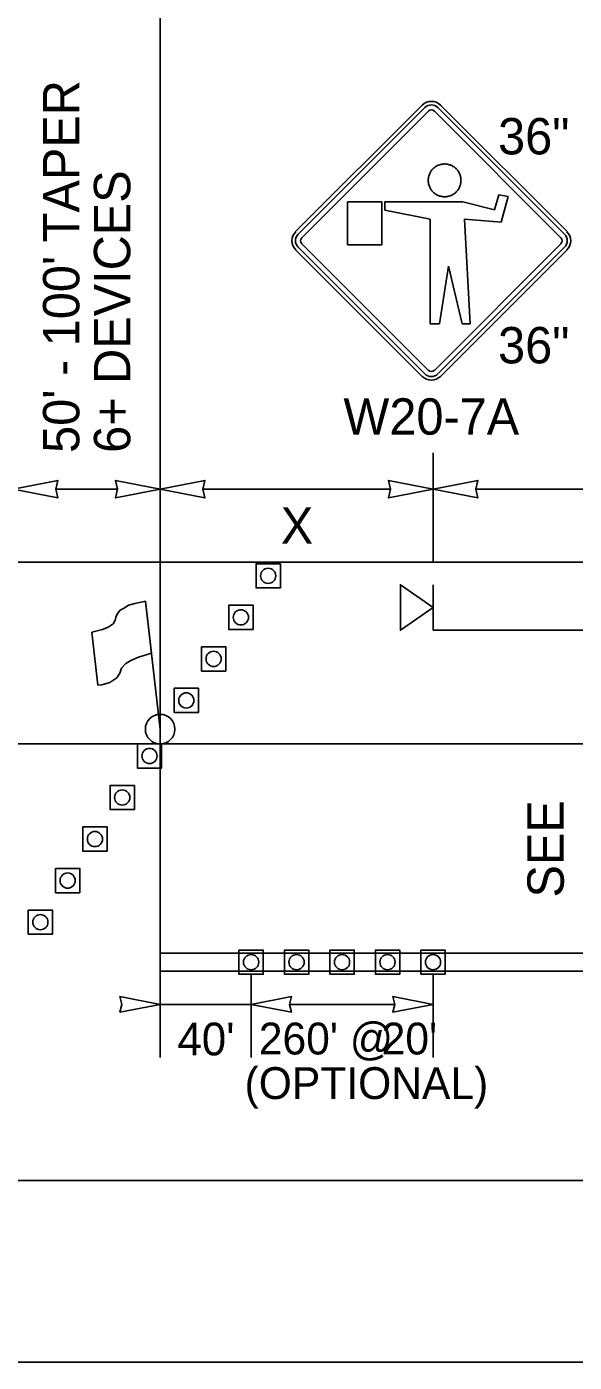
# Model space of a CAD drawing. Extents: x 99999.1 to 100095.7, y 99995 to 100010.7.
# Drawn here: x 100011.18 to 100012.384, y 100005.732 to 100008.67 of the extents above; entities that cross this region are included whole.
import ezdxf

# ---------------------------------------------------------------- set-up
doc = ezdxf.new("R2010")
doc.units = 0
for name, color, linetype in [('RD_ED_ShoulderPavedEdge', 7, 'Continuous'), ('RD_MK_LineDblYellowCenter', 7, 'Continuous'), ('RD_MK_LineEdgeWhite', 7, 'Continuous'), ('RD_MK_LineNoPass', 7, 'Continuous'), ('RD_MK_LineSkipCenter', 7, 'Continuous'), ('TR_SN_ConstructionSigns', 7, 'Continuous'), ('TR_WZ_FlaggingStation', 7, 'Continuous'), ('TR_WZ_PortableSignMountBlk-Org', 7, 'Continuous'), ('TR_WZ_TrafficCone', 7, 'Continuous'), ('TR_WZ_WorkZoneDetails', 7, 'Continuous'), ('TR_WZ_WorkZoneTextCurrent', 7, 'Continuous')]:
    doc.layers.add(name, color=color, linetype=linetype)

msp = doc.modelspace()

# ---------------------------------------------------------------- linework, layer by layer
at = {"layer": 'RD_ED_ShoulderPavedEdge'}
for p, q in [((100000.1076, 100007.4923), (100015.6424, 100007.4923)), ((100000.1076, 100005.7323), (100015.6424, 100005.7323))]:
    msp.add_line(p, q, dxfattribs=at)
at = {"layer": 'RD_MK_LineDblYellowCenter'}
for p, q in [((100012.2733, 100006.6323), (100015.6631, 100006.6323)), ((100012.2733, 100006.5923), (100015.6218, 100006.5923))]:
    msp.add_line(p, q, dxfattribs=at)
at = {"layer": 'RD_MK_LineEdgeWhite'}
for p, q in [((100000.1076, 100007.0923), (100015.6424, 100007.0923)), ((100000.1076, 100006.1323), (100015.6424, 100006.1323))]:
    msp.add_line(p, q, dxfattribs=at)
at = {"layer": 'RD_MK_LineNoPass'}
msp.add_line((100011.4733, 100006.5923), (100012.2733, 100006.5923), dxfattribs=at)
at = {"layer": 'RD_MK_LineSkipCenter'}
msp.add_lwpolyline([(100012.2733, 100006.6323), (100011.4733, 100006.6323)], dxfattribs=at)
at = {"layer": 'TR_SN_ConstructionSigns'}
for p, q in [((100012.0497, 100008.4972), (100011.7713, 100008.2188)), ((100012.0552, 100008.4917), (100011.7768, 100008.2132)), ((100011.7845, 100008.2055), (100012.063, 100008.4839)), ((100012.0762, 100008.4839), (100012.3546, 100008.2055)), ((100012.3624, 100008.2132), (100012.0839, 100008.4917)), ((100012.3679, 100008.2188), (100012.0895, 100008.4972)), ((100012.0797, 100008.3621), (100012.078, 100008.3611)), ((100012.0813, 100008.3631), (100012.0797, 100008.3621)), ((100012.083, 100008.364), (100012.0813, 100008.3631)), ((100012.0847, 100008.3648), (100012.083, 100008.364)), ((100012.0865, 100008.3655), (100012.0847, 100008.3648)), ((100012.0884, 100008.3661), (100012.0865, 100008.3655)), ((100012.0902, 100008.3666), (100012.0884, 100008.3661)), ((100012.0921, 100008.367), (100012.0902, 100008.3666)), ((100012.094, 100008.3673), (100012.0921, 100008.367)), ((100012.0959, 100008.3675), (100012.094, 100008.3673)), ((100012.0978, 100008.3676), (100012.0959, 100008.3675)), ((100012.0997, 100008.3676), (100012.0978, 100008.3676)), ((100012.1016, 100008.3675), (100012.0997, 100008.3676)), ((100012.1036, 100008.3673), (100012.1016, 100008.3675)), ((100012.1054, 100008.367), (100012.1036, 100008.3673)), ((100012.1073, 100008.3666), (100012.1054, 100008.367)), ((100012.1091, 100008.3661), (100012.1073, 100008.3666)), ((100012.111, 100008.3655), (100012.1091, 100008.3661)), ((100012.1128, 100008.3648), (100012.111, 100008.3655)), ((100012.1145, 100008.364), (100012.1128, 100008.3648)), ((100012.1162, 100008.3631), (100012.1145, 100008.364)), ((100012.1179, 100008.3621), (100012.1162, 100008.3631)), ((100012.1195, 100008.3611), (100012.1179, 100008.3621)), ((100012.063, 100008.3354), (100012.0628, 100008.3335)), ((100012.0628, 100008.3335), (100012.0628, 100008.3316)), ((100012.0632, 100008.3373), (100012.063, 100008.3354)), ((100012.0636, 100008.3392), (100012.0632, 100008.3373)), ((100012.064, 100008.3411), (100012.0636, 100008.3392)), ((100012.0646, 100008.3429), (100012.064, 100008.3411)), ((100012.0652, 100008.3447), (100012.0646, 100008.3429)), ((100012.066, 100008.3465), (100012.0652, 100008.3447)), ((100012.0668, 100008.3482), (100012.066, 100008.3465)), ((100012.0677, 100008.3499), (100012.0668, 100008.3482)), ((100012.0688, 100008.3516), (100012.0677, 100008.3499)), ((100012.0698, 100008.3531), (100012.0688, 100008.3516)), ((100012.071, 100008.3546), (100012.0698, 100008.3531)), ((100012.0723, 100008.3561), (100012.071, 100008.3546)), ((100012.0737, 100008.3574), (100012.0723, 100008.3561)), ((100012.075, 100008.3587), (100012.0737, 100008.3574)), ((100012.0765, 100008.3599), (100012.075, 100008.3587)), ((100012.078, 100008.3611), (100012.0765, 100008.3599)), ((100012.121, 100008.3599), (100012.1195, 100008.3611)), ((100012.1225, 100008.3587), (100012.121, 100008.3599)), ((100012.1239, 100008.3574), (100012.1225, 100008.3587)), ((100012.1252, 100008.3561), (100012.1239, 100008.3574)), ((100012.1265, 100008.3546), (100012.1252, 100008.3561)), ((100012.1276, 100008.3531), (100012.1265, 100008.3546)), ((100012.1288, 100008.3516), (100012.1276, 100008.3531)), ((100012.1298, 100008.3499), (100012.1288, 100008.3516)), ((100012.1307, 100008.3482), (100012.1298, 100008.3499)), ((100012.1315, 100008.3465), (100012.1307, 100008.3482)), ((100012.1323, 100008.3447), (100012.1315, 100008.3465)), ((100012.133, 100008.3429), (100012.1323, 100008.3447)), ((100012.1335, 100008.3411), (100012.133, 100008.3429)), ((100012.134, 100008.3392), (100012.1335, 100008.3411)), ((100012.1343, 100008.3373), (100012.134, 100008.3392)), ((100012.1346, 100008.3354), (100012.1343, 100008.3373)), ((100012.1347, 100008.3335), (100012.1346, 100008.3354)), ((100012.1348, 100008.3316), (100012.1347, 100008.3335)), ((100012.0628, 100008.3316), (100012.0628, 100008.3297)), ((100012.0628, 100008.3297), (100012.063, 100008.3278)), ((100012.063, 100008.3278), (100012.0632, 100008.3259)), ((100012.0632, 100008.3259), (100012.0636, 100008.324)), ((100012.0636, 100008.324), (100012.064, 100008.3221)), ((100012.064, 100008.3221), (100012.0646, 100008.3203)), ((100012.0646, 100008.3203), (100012.0652, 100008.3185)), ((100012.0652, 100008.3185), (100012.066, 100008.3167)), ((100012.066, 100008.3167), (100012.0668, 100008.315)), ((100012.0668, 100008.315), (100012.0677, 100008.3133)), ((100012.0677, 100008.3133), (100012.0688, 100008.3117)), ((100012.0688, 100008.3117), (100012.0698, 100008.3101)), ((100012.0698, 100008.3101), (100012.071, 100008.3086)), ((100012.071, 100008.3086), (100012.0723, 100008.3072)), ((100012.0723, 100008.3072), (100012.0737, 100008.3058)), ((100012.0737, 100008.3058), (100012.075, 100008.3045)), ((100012.075, 100008.3045), (100012.0765, 100008.3033)), ((100012.0765, 100008.3033), (100012.078, 100008.3021)), ((100012.1195, 100008.3021), (100012.121, 100008.3033)), ((100012.121, 100008.3033), (100012.1225, 100008.3045)), ((100012.1225, 100008.3045), (100012.1239, 100008.3058)), ((100012.1239, 100008.3058), (100012.1252, 100008.3072)), ((100012.1252, 100008.3072), (100012.1265, 100008.3086)), ((100012.1265, 100008.3086), (100012.1276, 100008.3101)), ((100012.1276, 100008.3101), (100012.1288, 100008.3117)), ((100012.1288, 100008.3117), (100012.1298, 100008.3133)), ((100012.1298, 100008.3133), (100012.1307, 100008.315)), ((100012.1307, 100008.315), (100012.1315, 100008.3167)), ((100012.1315, 100008.3167), (100012.1323, 100008.3185)), ((100012.1323, 100008.3185), (100012.133, 100008.3203)), ((100012.133, 100008.3203), (100012.1335, 100008.3221)), ((100012.1335, 100008.3221), (100012.134, 100008.324)), ((100012.134, 100008.324), (100012.1343, 100008.3259)), ((100012.1343, 100008.3259), (100012.1346, 100008.3278)), ((100012.1346, 100008.3278), (100012.1347, 100008.3297)), ((100012.1347, 100008.3297), (100012.1348, 100008.3316)), ((100011.8853, 100008.2843), (100011.8853, 100008.1896)), ((100011.9607, 100008.2843), (100011.8853, 100008.2843)), ((100011.9607, 100008.1896), (100011.9607, 100008.2843)), ((100012.139, 100008.2843), (100011.9677, 100008.2843)), ((100011.9677, 100008.2843), (100011.9677, 100008.2662)), ((100012.078, 100008.3021), (100012.0797, 100008.3011)), ((100012.0797, 100008.3011), (100012.0813, 100008.3001)), ((100012.0813, 100008.3001), (100012.083, 100008.2992)), ((100012.083, 100008.2992), (100012.0847, 100008.2984)), ((100012.0847, 100008.2984), (100012.0865, 100008.2977)), ((100012.0865, 100008.2977), (100012.0884, 100008.2971)), ((100012.0884, 100008.2971), (100012.0902, 100008.2966)), ((100012.0902, 100008.2966), (100012.0921, 100008.2962)), ((100012.0921, 100008.2962), (100012.094, 100008.2959)), ((100012.094, 100008.2959), (100012.0959, 100008.2957)), ((100012.0959, 100008.2957), (100012.0978, 100008.2956)), ((100012.0978, 100008.2956), (100012.0997, 100008.2956)), ((100012.0997, 100008.2956), (100012.1016, 100008.2957)), ((100012.1016, 100008.2957), (100012.1036, 100008.2959)), ((100012.1036, 100008.2959), (100012.1054, 100008.2962)), ((100012.1054, 100008.2962), (100012.1073, 100008.2966)), ((100012.1073, 100008.2966), (100012.1091, 100008.2971)), ((100012.1091, 100008.2971), (100012.111, 100008.2977)), ((100012.111, 100008.2977), (100012.1128, 100008.2984)), ((100012.1128, 100008.2984), (100012.1145, 100008.2992)), ((100012.1145, 100008.2992), (100012.1162, 100008.3001)), ((100012.1162, 100008.3001), (100012.1179, 100008.3011)), ((100012.1179, 100008.3011), (100012.1195, 100008.3021)), ((100012.2086, 100008.2671), (100012.139, 100008.2843)), ((100012.2183, 100008.3), (100012.2086, 100008.2671)), ((100012.2382, 100008.2964), (100012.2183, 100008.3)), ((100012.2232, 100008.2396), (100012.2382, 100008.2964)), ((100011.9677, 100008.2662), (100012.0672, 100008.2464)), ((100012.0672, 100008.2464), (100012.0672, 100008.0161)), ((100012.1553, 100008.0161), (100012.1422, 100008.2465)), ((100012.1422, 100008.2465), (100012.2232, 100008.2396)), ((100012.063, 100007.9138), (100011.7845, 100008.1923)), ((100011.8853, 100008.1896), (100011.9607, 100008.1896)), ((100012.3546, 100008.1923), (100012.0762, 100007.9138)), ((100011.7713, 100008.179), (100012.0497, 100007.9006)), ((100011.7768, 100008.1845), (100012.0552, 100007.9061)), ((100012.0839, 100007.9061), (100012.3624, 100008.1845)), ((100012.0895, 100007.9006), (100012.3679, 100008.179)), ((100012.0874, 100008.0161), (100012.107, 100008.1428)), ((100012.107, 100008.1428), (100012.1373, 100008.0161)), ((100012.0672, 100008.0161), (100012.0874, 100008.0161)), ((100012.1373, 100008.0161), (100012.1553, 100008.0161))]:
    msp.add_line(p, q, dxfattribs=at)
for centre, radius, start, end in [((100012.0696, 100008.4773), 0.0281, 45, 135), ((100012.0696, 100008.4773), 0.0203, 45, 135), ((100012.0696, 100008.4773), 0.00937, 45, 135), ((100011.7912, 100008.1989), 0.0281, 135, 225), ((100012.348, 100008.1989), 0.0281, 315, 45), ((100011.7912, 100008.1989), 0.0203, 135, 225), ((100011.7912, 100008.1989), 0.00937, 135, 225), ((100012.348, 100008.1989), 0.00937, 315, 45), ((100012.348, 100008.1989), 0.0203, 315, 45), ((100012.0696, 100007.9205), 0.0281, 225, 315), ((100012.0696, 100007.9205), 0.0203, 225, 315), ((100012.0696, 100007.9205), 0.00937, 225, 315)]:
    msp.add_arc(centre, radius, start, end, dxfattribs=at)
at = {"layer": 'TR_WZ_FlaggingStation'}
for p, q in [((100011.4543, 100007.2917), (100011.4413, 100007.4061)), ((100011.4733, 100007.1248), (100011.4413, 100007.4058)), ((100011.3233, 100007.3383), (100011.3366, 100007.2211)), ((100011.4543, 100007.2917), (100011.4543, 100007.2917))]:
    msp.add_line(p, q, dxfattribs=at)
for points in [[(100011.4413, 100007.4061), (100011.4355, 100007.4048), (100011.4177, 100007.4014), (100011.4039, 100007.3972), (100011.3942, 100007.3911), (100011.3857, 100007.3864), (100011.38, 100007.3796), (100011.3757, 100007.3717), (100011.3752, 100007.3655), (100011.3698, 100007.3563), (100011.359, 100007.3489), (100011.3466, 100007.3437), (100011.3233, 100007.3383)], [(100011.3366, 100007.2211), (100011.3448, 100007.2225), (100011.3624, 100007.2271), (100011.3781, 100007.2376), (100011.3846, 100007.2482), (100011.3885, 100007.2585), (100011.3976, 100007.2694), (100011.4086, 100007.2756), (100011.4259, 100007.2827), (100011.4543, 100007.2917)]]:
    msp.add_lwpolyline(points, dxfattribs=at)
msp.add_circle((100011.4733, 100007.1248), 0.0325, dxfattribs=at)
at = {"layer": 'TR_WZ_PortableSignMountBlk-Org'}
msp.add_line((100012.0733, 100007.4422), (100012.0733, 100007.3422), dxfattribs=at)
msp.add_lwpolyline([(100012.0733, 100007.3923), (100012.0015, 100007.3422), (100012.0015, 100007.4422)], close=True, dxfattribs=at)
at = {"layer": 'TR_WZ_TrafficCone'}
for points in [[(100011.6843, 100007.4886), (100011.7376, 100007.4886), (100011.7376, 100007.4352), (100011.6843, 100007.4352), (100011.6843, 100007.4886)], [(100011.6843, 100007.4352), (100011.7376, 100007.4352), (100011.7376, 100007.4886), (100011.6843, 100007.4886), (100011.6843, 100007.4352)], [(100011.6243, 100007.3972), (100011.6776, 100007.3972), (100011.6776, 100007.3439), (100011.6243, 100007.3439), (100011.6243, 100007.3972)], [(100011.6243, 100007.3439), (100011.6776, 100007.3439), (100011.6776, 100007.3972), (100011.6243, 100007.3972), (100011.6243, 100007.3439)], [(100011.5643, 100007.3059), (100011.6176, 100007.3059), (100011.6176, 100007.2526), (100011.5643, 100007.2526), (100011.5643, 100007.3059)], [(100011.5643, 100007.2526), (100011.6176, 100007.2526), (100011.6176, 100007.3059), (100011.5643, 100007.3059), (100011.5643, 100007.2526)], [(100011.5043, 100007.2146), (100011.5576, 100007.2146), (100011.5576, 100007.1612), (100011.5043, 100007.1612), (100011.5043, 100007.2146)], [(100011.5043, 100007.1612), (100011.5576, 100007.1612), (100011.5576, 100007.2146), (100011.5043, 100007.2146), (100011.5043, 100007.1612)], [(100011.4766, 100007.0923), (100011.4233, 100007.0923), (100011.4233, 100007.039), (100011.4766, 100007.039), (100011.4766, 100007.0923)], [(100011.4766, 100007.039), (100011.4233, 100007.039), (100011.4233, 100007.0923), (100011.4766, 100007.0923), (100011.4766, 100007.039)], [(100011.4166, 100007.001), (100011.3633, 100007.001), (100011.3633, 100006.9477), (100011.4166, 100006.9477), (100011.4166, 100007.001)], [(100011.4166, 100006.9477), (100011.3633, 100006.9477), (100011.3633, 100007.001), (100011.4166, 100007.001), (100011.4166, 100006.9477)], [(100011.3566, 100006.9097), (100011.3033, 100006.9097), (100011.3033, 100006.8563), (100011.3566, 100006.8563), (100011.3566, 100006.9097)], [(100011.3566, 100006.8563), (100011.3033, 100006.8563), (100011.3033, 100006.9097), (100011.3566, 100006.9097), (100011.3566, 100006.8563)], [(100011.2966, 100006.8183), (100011.2433, 100006.8183), (100011.2433, 100006.765), (100011.2966, 100006.765), (100011.2966, 100006.8183)], [(100011.2966, 100006.765), (100011.2433, 100006.765), (100011.2433, 100006.8183), (100011.2966, 100006.8183), (100011.2966, 100006.765)], [(100011.2366, 100006.727), (100011.1833, 100006.727), (100011.1833, 100006.6737), (100011.2366, 100006.6737), (100011.2366, 100006.727)], [(100011.2366, 100006.6737), (100011.1833, 100006.6737), (100011.1833, 100006.727), (100011.2366, 100006.727), (100011.2366, 100006.6737)], [(100011.7, 100006.639), (100011.6467, 100006.639), (100011.6467, 100006.5857), (100011.7, 100006.5857), (100011.7, 100006.639)], [(100011.7, 100006.5857), (100011.6467, 100006.5857), (100011.6467, 100006.639), (100011.7, 100006.639), (100011.7, 100006.5857)], [(100011.8, 100006.639), (100011.7467, 100006.639), (100011.7467, 100006.5857), (100011.8, 100006.5857), (100011.8, 100006.639)], [(100011.8, 100006.5857), (100011.7467, 100006.5857), (100011.7467, 100006.639), (100011.8, 100006.639), (100011.8, 100006.5857)], [(100011.9, 100006.639), (100011.8467, 100006.639), (100011.8467, 100006.5857), (100011.9, 100006.5857), (100011.9, 100006.639)], [(100011.9, 100006.5857), (100011.8467, 100006.5857), (100011.8467, 100006.639), (100011.9, 100006.639), (100011.9, 100006.5857)], [(100012, 100006.639), (100011.9467, 100006.639), (100011.9467, 100006.5857), (100012, 100006.5857), (100012, 100006.639)], [(100012, 100006.5857), (100011.9467, 100006.5857), (100011.9467, 100006.639), (100012, 100006.639), (100012, 100006.5857)], [(100012.1, 100006.639), (100012.0467, 100006.639), (100012.0467, 100006.5857), (100012.1, 100006.5857), (100012.1, 100006.639)], [(100012.1, 100006.5857), (100012.0467, 100006.5857), (100012.0467, 100006.639), (100012.1, 100006.639), (100012.1, 100006.5857)]]:
    msp.add_lwpolyline(points, dxfattribs=at)
for centre in [(100011.7109, 100007.4619), (100011.6509, 100007.3706), (100011.5909, 100007.2792), (100011.5309, 100007.1879), (100011.45, 100007.0657), (100011.39, 100006.9743), (100011.33, 100006.883), (100011.27, 100006.7917), (100011.21, 100006.7003), (100011.6733, 100006.6123), (100011.7733, 100006.6123), (100011.8733, 100006.6123), (100011.9733, 100006.6123), (100012.0733, 100006.6123)]:
    msp.add_circle(centre, 0.0167, dxfattribs=at)
at = {"layer": 'TR_WZ_WorkZoneDetails'}
for p, q in [((100011.4733, 100007.0923), (100011.4733, 100008.9491)), ((100012.0733, 100007.4923), (100012.0733, 100007.7323)), ((100011.3796, 100007.6523), (100011.2437, 100007.6523)), ((100011.5671, 100007.6523), (100011.9796, 100007.6523)), ((100012.1671, 100007.6523), (100012.7296, 100007.6523)), ((100012.0733, 100007.3422), (100015.1733, 100007.3422)), ((100011.4733, 100007.0923), (100011.4733, 100006.4023)), ((100011.6733, 100006.5857), (100011.6733, 100006.4023)), ((100012.0733, 100006.5857), (100012.0733, 100006.4023)), ((100011.6733, 100006.5193), (100011.4733, 100006.5193)), ((100011.989, 100006.5193), (100011.7577, 100006.5193))]:
    msp.add_line(p, q, dxfattribs=at)
for points in [[(100011.15, 100007.6523), (100011.2483, 100007.6331), (100011.2437, 100007.6523), (100011.2483, 100007.6716)], [(100011.4733, 100007.6523), (100011.3751, 100007.6331), (100011.3796, 100007.6523), (100011.3751, 100007.6716)], [(100011.4733, 100007.6523), (100011.5716, 100007.6331), (100011.5671, 100007.6523), (100011.5716, 100007.6716)], [(100012.0733, 100007.6523), (100011.9751, 100007.6331), (100011.9796, 100007.6523), (100011.9751, 100007.6716)], [(100012.0733, 100007.6523), (100012.1716, 100007.6331), (100012.1671, 100007.6523), (100012.1716, 100007.6716)], [(100011.4733, 100006.5193), (100011.3849, 100006.502), (100011.389, 100006.5193), (100011.3849, 100006.5367)], [(100011.6733, 100006.5193), (100011.7618, 100006.502), (100011.7577, 100006.5193), (100011.7618, 100006.5367)], [(100012.0733, 100006.5193), (100011.9849, 100006.502), (100011.989, 100006.5193), (100011.9849, 100006.5367)]]:
    msp.add_lwpolyline(points, close=True, dxfattribs=at)

# ---------------------------------------------------------------- texts
at = {"layer": 'TR_SN_ConstructionSigns'}
for s, p in [('36"', (100012.2163, 100008.3887)), ('36"', (100012.2163, 100007.9291)), ('W20-7A', (100011.8763, 100007.7723))]:
    msp.add_text(s, height=0.08, rotation=360, dxfattribs=at).set_placement(p)
at = {"layer": 'TR_WZ_WorkZoneDetails'}
msp.add_text('SEE', height=0.08, rotation=90, dxfattribs=at).set_placement((100012.3608, 100006.7544))
at = {"layer": 'TR_WZ_WorkZoneTextCurrent'}
for s, p in [("50' - 100' TAPER", (100011.2957, 100007.7323)), ('6+ DEVICES', (100011.4077, 100007.7323))]:
    msp.add_text(s, height=0.08, rotation=90, dxfattribs=at).set_placement(p)
for s, height, p in [('X', 0.08, (100011.7386, 100007.5323)), ("260' @", 0.07, (100011.6903, 100006.4093)), ("40'", 0.072, (100011.5114, 100006.4073)), ("20'", 0.07, (100011.9604, 100006.4093)), ('(OPTIONAL)', 0.07, (100011.659, 100006.3113))]:
    msp.add_text(s, height=height, dxfattribs=at).set_placement(p)

doc.saveas('drawing.dxf')
